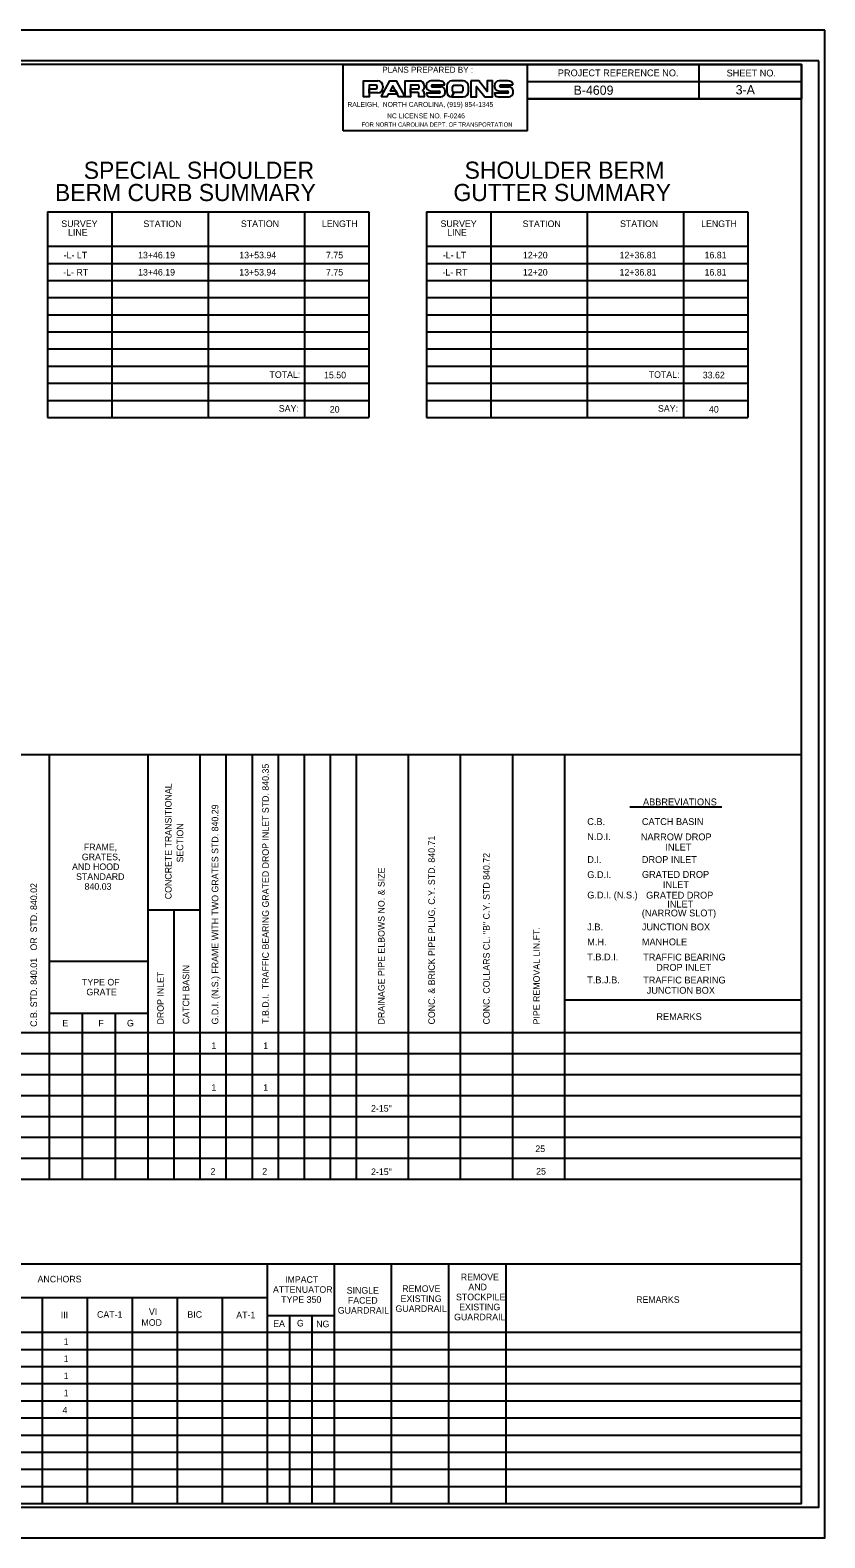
# Model space of a CAD drawing. Extents: x 573850.4 to 573884, y -53328.4 to -53306.4.
# Drawn here: x 573872.44 to 573884.04, y -53328.38 to -53306.38 of the extents above; entities that cross this region are included whole.
import ezdxf

# ---------------------------------------------------------------- set-up
doc = ezdxf.new("R2010")
doc.units = 0
for name, color, linetype in [('Old_Level_2', 7, 'Continuous'), ('Sheet Cutting Line CELL', 7, 'Continuous'), ('Sheet Data Field CELL', 7, 'Continuous'), ('Sheet Pipe Summary CELL', 7, 'Continuous'), ('Sheet Pipe Summary Grid CELL', 7, 'Continuous'), ('Sheet Plot Border Inside CELL', 7, 'Continuous'), ('Sheet Plot Border Outside CELL', 7, 'Continuous'), ('Sheet Summary Combination CELL', 7, 'Continuous'), ('Sheet Summary Combination Grid CELL', 7, 'Continuous')]:
    doc.layers.add(name, color=color, linetype=linetype)

msp = doc.modelspace()

# ---------------------------------------------------------------- linework, layer by layer
at = {"layer": 'Old_Level_2'}
for p, q in [((573877.008, -53306.879), (573879.696, -53306.879)), ((573877.008, -53307.848), (573877.008, -53306.879)), ((573879.696, -53307.848), (573879.696, -53306.879)), ((573877.504, -53307.215), (573877.504, -53307.201)), ((573877.586, -53307.196), (573877.586, -53307.219)), ((573878.114, -53307.219), (573878.114, -53307.193)), ((573878.19, -53307.186), (573878.19, -53307.221)), ((573878.219, -53307.192), (573878.219, -53307.201)), ((573878.278, -53307.265), (573878.409, -53307.268)), ((573878.419, -53307.12), (573878.286, -53307.12)), ((573878.308, -53307.179), (573878.488, -53307.179)), ((573878.436, -53307.209), (573878.308, -53307.209)), ((573878.494, -53307.288), (573878.494, -53307.27)), ((573878.521, -53307.199), (573878.521, -53307.277)), ((573878.591, -53307.354), (573878.623, -53307.291)), ((573878.757, -53307.12), (573878.594, -53307.12)), ((573878.6, -53307.267), (573878.6, -53307.207)), ((573878.623, -53307.182), (573878.729, -53307.182)), ((573878.751, -53307.207), (573878.751, -53307.267)), ((573878.836, -53307.271), (573878.836, -53307.205)), ((573879.214, -53307.192), (573879.214, -53307.201)), ((573879.273, -53307.265), (573879.404, -53307.268)), ((573879.415, -53307.12), (573879.282, -53307.12)), ((573879.303, -53307.179), (573879.483, -53307.179)), ((573879.432, -53307.209), (573879.303, -53307.209)), ((573879.489, -53307.288), (573879.489, -53307.27)), ((573878.295, -53307.354), (573878.432, -53307.354)), ((573878.591, -53307.354), (573878.76, -53307.354)), ((573879.29, -53307.354), (573879.427, -53307.354)), ((573879.696, -53307.848), (573877.008, -53307.848))]:
    msp.add_line(p, q, dxfattribs=at)
for points in [[(573877.487, -53307.182), (573877.384, -53307.182), (573877.384, -53307.236), (573877.385, -53307.296), (573877.385, -53307.354), (573877.302, -53307.354), (573877.302, -53307.12), (573877.514, -53307.12)], [(573877.514, -53307.296), (573877.385, -53307.296), (573877.384, -53307.236), (573877.484, -53307.236)], [(573878.104, -53307.183), (573877.988, -53307.183), (573877.988, -53307.235), (573877.988, -53307.291), (573877.988, -53307.354), (573877.911, -53307.354), (573877.911, -53307.12), (573878.128, -53307.12)], [(573878.19, -53307.303), (573878.19, -53307.354), (573878.111, -53307.354), (573878.111, -53307.3), (573878.101, -53307.291), (573877.988, -53307.291), (573877.988, -53307.235), (573878.1, -53307.235)], [(573878.409, -53307.297), (573878.222, -53307.297), (573878.222, -53307.302)], [(573878.729, -53307.291), (573878.623, -53307.291), (573878.591, -53307.354), (573878.76, -53307.354)], [(573879.404, -53307.297), (573879.217, -53307.297), (573879.217, -53307.302)]]:
    msp.add_lwpolyline(points, dxfattribs=at)
for points in [[(573877.559, -53307.354), (573877.688, -53307.12), (573877.781, -53307.12), (573877.908, -53307.354), (573877.821, -53307.354), (573877.732, -53307.19), (573877.69, -53307.265), (573877.773, -53307.265), (573877.799, -53307.314), (573877.665, -53307.314), (573877.644, -53307.354)], [(573878.872, -53307.12), (573878.872, -53307.354), (573878.951, -53307.354), (573878.951, -53307.202), (573879.073, -53307.354), (573879.185, -53307.354), (573879.185, -53307.12), (573879.108, -53307.12), (573879.108, -53307.276), (573878.985, -53307.12)]]:
    msp.add_lwpolyline(points, close=True, dxfattribs=at)
for centre, major_axis, ratio, start_param, end_param in [((573877.484, -53307.215), (0, 0.0214), 0.93676, 3.141593, 4.712389), ((573877.487, -53307.201), (0, 0.0184), 0.93676, 4.712389, 6.283185), ((573877.514, -53307.196), (0, 0.0765), 0.93676, 4.712389, 6.283185), ((573877.514, -53307.219), (0, 0.0765), 0.93676, 3.141593, 4.712389), ((573878.1, -53307.219), (0, 0.0153), 0.934072, 3.141593, 4.712389), ((573878.104, -53307.193), (0, 0.0107), 0.934072, 4.712389, 6.283185), ((573878.128, -53307.186), (0, 0.0658), 0.934072, 4.712389, 6.283185), ((573878.152, -53307.221), (0, 0.0398), 0.934072, 3.34512, 4.712389), ((573878.147, -53307.303), (0, 0.0459), 0.934072, 4.712389, 5.969561), ((573878.286, -53307.192), (0, 0.0719), 0.934072, 0, 1.570796), ((573878.279, -53307.201), (0, -0.0643), 0.934072, 4.712389, 6.260753), ((573878.266, -53307.302), (0, -0.0474), 0.934072, 4.712389, 5.988639), ((573878.308, -53307.194), (0, 0.0145), 0.934072, 0, 3.141593), ((573878.409, -53307.283), (0, 0.0145), 0.934072, 3.141593, 6.283185), ((573878.419, -53307.219), (0, 0.0994), 0.934072, 5.902203, 6.283185), ((573878.432, -53307.288), (0, 0.0658), 0.934072, 3.141593, 4.712389), ((573878.437, -53307.27), (0, 0.0612), 0.934072, 4.712389, 6.283185), ((573878.434, -53307.181), (0, 0.0582), 0.934072, 4.738699, 5.901866), ((573878.594, -53307.199), (0, 0.0796), 0.924824, 0, 1.570796), ((573878.591, -53307.277), (0, -0.0765), 0.924824, 4.712389, 6.283185), ((573878.623, -53307.207), (0, -0.0245), 0.924824, 3.141593, 4.712389), ((573878.623, -53307.267), (0, -0.0245), 0.924824, 4.712389, 6.283185), ((573878.729, -53307.207), (0, 0.0245), 0.924824, 4.712389, 6.283185), ((573878.729, -53307.267), (0, 0.0245), 0.924824, 3.141593, 4.712389), ((573878.757, -53307.205), (0, 0.0857), 0.924824, 4.712389, 6.283185), ((573878.76, -53307.271), (0, 0.0826), 0.924824, 3.141593, 4.712389), ((573879.282, -53307.192), (0, 0.0719), 0.934072, 0, 1.570796), ((573879.274, -53307.201), (0, -0.0643), 0.934072, 4.712389, 6.260753), ((573879.262, -53307.302), (0, -0.0474), 0.934072, 4.712389, 5.988639), ((573879.303, -53307.194), (0, 0.0145), 0.934072, 0, 3.141593), ((573879.405, -53307.283), (0, 0.0145), 0.934072, 3.141593, 6.283185), ((573879.415, -53307.219), (0, 0.0994), 0.934072, 5.902203, 6.283185), ((573879.427, -53307.288), (0, 0.0658), 0.934072, 3.141593, 4.712389), ((573879.432, -53307.27), (0, 0.0612), 0.934072, 4.712389, 6.283185), ((573879.429, -53307.181), (0, 0.0582), 0.934072, 4.738699, 5.901866), ((573878.295, -53307.201), (0, 0.153), 0.934072, 2.847261, 3.141593), ((573879.29, -53307.201), (0, 0.153), 0.934072, 2.847261, 3.141593)]:
    msp.add_ellipse(centre, major_axis=major_axis, ratio=ratio, start_param=start_param, end_param=end_param, dxfattribs=at)
at = {"layer": 'Sheet Cutting Line CELL'}
for p, q in [((573884.037, -53306.379), (573850.357, -53306.379)), ((573850.357, -53328.379), (573884.037, -53328.379))]:
    msp.add_line(p, q, dxfattribs=at)
at = {"layer": 'Sheet Pipe Summary CELL'}
msp.add_line((573882.532, -53317.719), (573881.192, -53317.719), dxfattribs=at)
at = {"layer": 'Sheet Pipe Summary Grid CELL'}
for p, q in [((573883.697, -53316.954), (573853.697, -53316.956)), ((573872.722, -53323.15), (573872.722, -53316.955)), ((573874.161, -53323.15), (573874.161, -53316.954)), ((573874.921, -53323.15), (573874.921, -53316.954)), ((573875.301, -53323.15), (573875.301, -53316.954)), ((573875.681, -53323.15), (573875.681, -53316.954)), ((573876.061, -53323.15), (573876.061, -53316.954)), ((573876.441, -53323.15), (573876.441, -53316.954)), ((573876.821, -53323.15), (573876.821, -53316.954)), ((573877.201, -53323.15), (573877.201, -53316.954)), ((573877.961, -53323.15), (573877.961, -53316.954)), ((573877.961, -53323.15), (573877.961, -53316.954)), ((573878.721, -53323.15), (573878.721, -53316.954)), ((573878.721, -53323.15), (573878.721, -53316.954)), ((573879.481, -53323.15), (573879.481, -53316.954)), ((573879.481, -53323.15), (573879.481, -53316.954)), ((573880.241, -53323.15), (573880.241, -53316.954)), ((573880.241, -53323.15), (573880.241, -53316.954)), ((573874.921, -53319.219), (573874.161, -53319.219)), ((573874.541, -53323.15), (573874.541, -53319.219)), ((573874.161, -53319.97), (573872.722, -53319.97)), ((573874.161, -53320.726), (573872.722, -53320.726)), ((573873.202, -53323.15), (573873.202, -53320.726)), ((573873.682, -53323.15), (573873.682, -53320.726)), ((573883.697, -53320.535), (573880.241, -53320.535)), ((573883.697, -53321.012), (573853.697, -53321.012)), ((573883.697, -53321.318), (573853.697, -53321.318)), ((573883.697, -53321.318), (573853.697, -53321.318)), ((573883.697, -53321.623), (573853.697, -53321.623)), ((573883.697, -53321.928), (573853.697, -53321.928)), ((573883.697, -53322.234), (573853.697, -53322.234)), ((573883.697, -53322.538), (573853.697, -53322.538)), ((573883.697, -53322.844), (573853.697, -53322.844)), ((573883.697, -53323.15), (573853.697, -53323.15))]:
    msp.add_line(p, q, dxfattribs=at)
at = {"layer": 'Sheet Plot Border Inside CELL'}
msp.add_lwpolyline([(573883.947, -53306.828), (573850.617, -53306.828), (573850.617, -53327.93), (573883.947, -53327.93)], close=True, dxfattribs=at)
at = {"layer": 'Sheet Plot Border Outside CELL'}
msp.add_lwpolyline([(573884.037, -53306.379), (573850.357, -53306.379), (573850.357, -53328.379), (573884.037, -53328.379)], close=True, dxfattribs=at)
at = {"layer": 'Sheet Summary Combination CELL'}
for p, q in [((573882.197, -53306.88), (573882.197, -53307.38)), ((573879.696, -53307.13), (573883.697, -53307.13)), ((573879.696, -53307.38), (573883.697, -53307.38)), ((573875.515, -53309.033), (573875.515, -53309.033)), ((573875.64, -53309.035), (573875.64, -53309.035)), ((573875.821, -53309.031), (573875.821, -53309.031)), ((573875.933, -53309.033), (573875.933, -53309.033)), ((573881.05, -53309.033), (573881.05, -53309.033)), ((573881.175, -53309.035), (573881.175, -53309.035)), ((573881.356, -53309.031), (573881.356, -53309.031)), ((573881.468, -53309.033), (573881.468, -53309.033))]:
    msp.add_line(p, q, dxfattribs=at)
for points in [[(573883.697, -53306.879), (573853.697, -53306.879), (573853.697, -53327.879), (573883.697, -53327.879)], [(573879.696, -53306.879), (573883.697, -53306.879), (573883.697, -53307.38), (573879.696, -53307.38)]]:
    msp.add_lwpolyline(points, close=True, dxfattribs=at)
at = {"layer": 'Sheet Summary Combination Grid CELL'}
for p, q in [((573872.69, -53309.032), (573877.379, -53309.032)), ((573872.69, -53309.032), (573872.69, -53312.032)), ((573873.628, -53309.032), (573873.628, -53312.032)), ((573875.035, -53309.032), (573875.035, -53312.032)), ((573876.441, -53309.032), (573876.441, -53312.032)), ((573877.379, -53309.032), (573877.379, -53312.032)), ((573878.225, -53309.032), (573882.914, -53309.032)), ((573878.225, -53309.032), (573878.225, -53312.032)), ((573879.163, -53309.032), (573879.163, -53312.032)), ((573880.57, -53309.032), (573880.57, -53312.032)), ((573881.976, -53309.032), (573881.976, -53312.032)), ((573882.914, -53309.032), (573882.914, -53312.032)), ((573872.69, -53309.532), (573877.379, -53309.532)), ((573878.225, -53309.532), (573882.914, -53309.532)), ((573872.69, -53309.782), (573877.379, -53309.782)), ((573878.225, -53309.782), (573882.914, -53309.782)), ((573872.69, -53310.032), (573877.379, -53310.032)), ((573878.225, -53310.032), (573882.914, -53310.032)), ((573872.69, -53310.282), (573877.379, -53310.282)), ((573878.225, -53310.282), (573882.914, -53310.282)), ((573872.69, -53310.532), (573877.379, -53310.532)), ((573878.225, -53310.532), (573882.914, -53310.532)), ((573872.69, -53310.782), (573877.379, -53310.782)), ((573872.69, -53310.782), (573877.379, -53310.782)), ((573878.225, -53310.782), (573882.914, -53310.782)), ((573878.225, -53310.782), (573882.914, -53310.782)), ((573872.69, -53311.032), (573877.379, -53311.032)), ((573878.225, -53311.032), (573882.914, -53311.032)), ((573872.69, -53311.282), (573877.379, -53311.282)), ((573878.225, -53311.282), (573882.914, -53311.282)), ((573872.69, -53311.532), (573877.379, -53311.532)), ((573878.225, -53311.532), (573882.914, -53311.532)), ((573872.69, -53311.782), (573877.379, -53311.782)), ((573878.225, -53311.782), (573882.914, -53311.782)), ((573872.69, -53312.032), (573877.379, -53312.032)), ((573878.225, -53312.032), (573882.914, -53312.032)), ((573853.697, -53324.379), (573883.697, -53324.379)), ((573875.896, -53324.379), (573875.896, -53327.879)), ((573876.873, -53324.379), (573876.873, -53327.879)), ((573877.709, -53324.379), (573877.709, -53327.879)), ((573878.545, -53324.379), (573878.545, -53327.879)), ((573879.382, -53324.379), (573879.382, -53327.879)), ((573875.896, -53324.879), (573866.353, -53324.879)), ((573872.615, -53324.879), (573872.615, -53327.879)), ((573873.271, -53324.879), (573873.271, -53327.879)), ((573873.927, -53324.879), (573873.927, -53327.879)), ((573874.584, -53324.879), (573874.584, -53327.879)), ((573875.24, -53324.879), (573875.24, -53327.879)), ((573875.896, -53325.134), (573876.868, -53325.134)), ((573876.221, -53325.134), (573876.222, -53327.879)), ((573876.548, -53325.134), (573876.549, -53327.879)), ((573853.697, -53325.379), (573883.697, -53325.379)), ((573853.697, -53325.629), (573883.697, -53325.629)), ((573853.697, -53325.879), (573883.697, -53325.879)), ((573853.697, -53326.129), (573883.697, -53326.129)), ((573853.697, -53326.379), (573883.697, -53326.379)), ((573853.697, -53326.629), (573883.697, -53326.629)), ((573853.697, -53326.879), (573883.697, -53326.879)), ((573853.697, -53327.129), (573883.697, -53327.129)), ((573853.697, -53327.379), (573883.697, -53327.379)), ((573853.697, -53327.629), (573883.697, -53327.629))]:
    msp.add_line(p, q, dxfattribs=at)

# ---------------------------------------------------------------- texts
at = {"layer": 'Old_Level_2'}
for s, height, rotation, p in [('PLANS PREPARED BY : ', 0.08829, 359.999, (573877.577, -53307.002)), ('RALEIGH,  NORTH CAROLINA, (919) 854-1345', 0.07151, 360, (573877.068, -53307.499)), ('FOR NORTH CAROLINA DEPT. OF TRANSPORTATION', 0.06203, 359.9999, (573877.274, -53307.788)), ('NC LICENSE NO. F-0246', 0.07151, 360, (573877.647, -53307.666))]:
    msp.add_text(s, height=height, rotation=rotation, dxfattribs=at).set_placement(p)
at = {"layer": 'Sheet Data Field CELL'}
for s, p in [('B-4609   ', (573880.369, -53307.323)), ('3-A', (573882.735, -53307.317))]:
    msp.add_text(s, height=0.135, dxfattribs=at).set_placement(p)
at = {"layer": 'Sheet Pipe Summary CELL'}
for s, height, rotation, p in [('T.B.D.I.  TRAFFIC BEARING GRATED DROP INLET STD. 840.35', 0.096, 90, (573875.921, -53320.879)), ('CONCRETE TRANSITIONAL', 0.096, 90, (573874.502, -53319.061)), ('G.D.I. (N.S.) FRAME WITH TWO GRATES STD. 840.29', 0.096, 90, (573875.184, -53320.888)), ('SECTION', 0.096, 90, (573874.673, -53318.524)), ('CONC. & BRICK PIPE PLUG, C.Y. STD. 840.71', 0.096, 90, (573878.345, -53320.888)), ('CONC. COLLARS CL. "B" C.Y. STD 840.72', 0.096, 90, (573879.145, -53320.888)), ('DRAINAGE PIPE ELBOWS NO. & SIZE', 0.096, 90, (573877.611, -53320.888)), ('C.B. STD. 840.01   OR  STD. 840.02', 0.096, 90, (573872.538, -53320.923)), ('GRATED DROP', 0.1, 0.0274, (573881.428, -53319.052)), ('INLET', 0.1, 0.0274, (573881.736, -53319.182)), ('(NARROW SLOT)', 0.1, 0.0274, (573881.365, -53319.312)), ('PIPE REMOVAL LIN.FT.', 0.096, 90, (573879.876, -53320.888)), ('CATCH BASIN', 0.096, 90, (573874.759, -53320.884)), ('DROP INLET', 0.096, 90, (573874.388, -53320.888))]:
    msp.add_text(s, height=height, rotation=rotation, dxfattribs=at).set_placement(p)
for s, height, p in [('ABBREVIATIONS', 0.1, (573881.383, -53317.691)), ('C.B.', 0.1, (573880.569, -53317.978)), ('CATCH BASIN', 0.1, (573881.366, -53317.978)), ('N.D.I.', 0.1, (573880.569, -53318.197)), ('NARROW DROP', 0.1, (573881.351, -53318.201)), ('FRAME,', 0.096, (573873.222, -53318.347)), ('INLET', 0.1, (573881.71, -53318.351)), ('AND HOOD', 0.096, (573873.049, -53318.635)), ('GRATES,', 0.096, (573873.192, -53318.491)), ('D.I.', 0.1, (573880.569, -53318.532)), ('DROP INLET', 0.1, (573881.366, -53318.532)), ('STANDARD', 0.096, (573873.108, -53318.779)), ('G.D.I.', 0.1, (573880.569, -53318.752)), ('GRATED DROP', 0.1, (573881.367, -53318.749)), ('840.03', 0.096, (573873.232, -53318.923)), ('G.D.I. (N.S.)', 0.1, (573880.569, -53319.05)), ('INLET', 0.1, (573881.674, -53318.899)), ('J.B.', 0.1, (573880.569, -53319.515)), ('JUNCTION BOX', 0.1, (573881.366, -53319.515)), ('M.H.', 0.1, (573880.569, -53319.734)), ('MANHOLE', 0.1, (573881.366, -53319.734)), ('T.B.D.I.', 0.1, (573880.569, -53319.953)), ('TRAFFIC BEARING', 0.1, (573881.385, -53319.955)), ('DROP INLET', 0.1, (573881.575, -53320.105)), ('TYPE OF', 0.096, (573873.194, -53320.319)), ('T.B.J.B.', 0.1, (573880.569, -53320.288)), ('TRAFFIC BEARING', 0.1, (573881.385, -53320.29)), ('GRATE', 0.096, (573873.259, -53320.463)), ('JUNCTION BOX', 0.1, (573881.437, -53320.44)), ('REMARKS', 0.1, (573881.578, -53320.824)), ('E', 0.096, (573872.909, -53320.917)), ('F', 0.096, (573873.433, -53320.917)), ('G', 0.096, (573873.851, -53320.917))]:
    msp.add_text(s, height=height, dxfattribs=at).set_placement(p)
at = {"layer": 'Sheet Summary Combination CELL'}
for s, height, p in [('PROJECT REFERENCE NO.', 0.1, (573880.14, -53307.053)), ('SHEET NO.', 0.1, (573882.603, -53307.055)), ('SURVEY', 0.096, (573872.893, -53309.252)), ('LINE', 0.096, (573872.991, -53309.378)), ('STATION', 0.096, (573874.091, -53309.253)), ('STATION', 0.096, (573875.514, -53309.252)), ('LENGTH', 0.096, (573876.696, -53309.252)), ('SURVEY', 0.096, (573878.427, -53309.252)), ('LINE', 0.096, (573878.526, -53309.378)), ('STATION', 0.096, (573879.626, -53309.253)), ('STATION', 0.096, (573881.048, -53309.252)), ('LENGTH', 0.096, (573882.231, -53309.252)), ('-L- LT', 0.096, (573872.927, -53309.71)), ('13+46.19', 0.096, (573874.013, -53309.71)), ('13+53.94', 0.096, (573875.49, -53309.71)), ('7.75', 0.096, (573876.756, -53309.71)), ('-L- LT', 0.096, (573878.461, -53309.71)), ('12+20', 0.096, (573879.63, -53309.71)), ('12+36.81', 0.096, (573881.041, -53309.71)), ('16.81', 0.096, (573882.281, -53309.71)), ('-L- RT', 0.096, (573872.921, -53309.96)), ('13+46.19', 0.096, (573874.013, -53309.96)), ('13+53.94', 0.096, (573875.49, -53309.96)), ('7.75', 0.096, (573876.756, -53309.96)), ('-L- RT', 0.096, (573878.456, -53309.96)), ('12+20', 0.096, (573879.63, -53309.96)), ('12+36.81', 0.096, (573881.041, -53309.96)), ('16.81', 0.096, (573882.281, -53309.96)), ('TOTAL:', 0.096, (573875.931, -53311.453)), ('15.50', 0.096, (573876.727, -53311.46)), ('TOTAL:', 0.096, (573881.466, -53311.453)), ('33.62', 0.096, (573882.255, -53311.46)), ('SAY:', 0.096, (573876.067, -53311.947)), ('20', 0.096, (573876.811, -53311.96)), ('SAY:', 0.096, (573881.601, -53311.947)), ('40', 0.096, (573882.345, -53311.96)), ('1', 0.096, (573875.084, -53321.246)), ('1', 0.096, (573875.84, -53321.246)), ('1', 0.096, (573875.084, -53321.856)), ('1', 0.096, (573875.84, -53321.856)), ('2-15"', 0.096, (573877.413, -53322.161)), ('25', 0.096, (573879.811, -53322.75)), ('2', 0.096, (573875.07, -53323.079)), ('2', 0.096, (573875.826, -53323.079)), ('2-15"', 0.096, (573877.413, -53323.086)), ('25', 0.096, (573879.823, -53323.079)), ('ANCHORS', 0.096, (573872.546, -53324.652)), ('IMPACT', 0.096, (573876.158, -53324.658)), ('REMOVE', 0.096, (573877.868, -53324.791)), ('REMOVE', 0.096, (573878.723, -53324.621)), ('AND', 0.096, (573878.834, -53324.767)), ('ATTENUATOR', 0.096, (573875.982, -53324.804)), ('TYPE 350', 0.096, (573876.102, -53324.95)), ('SINGLE', 0.096, (573877.058, -53324.816)), ('FACED', 0.096, (573877.075, -53324.962)), ('EXISTING', 0.096, (573877.844, -53324.937)), ('STOCKPILE', 0.096, (573878.653, -53324.913)), ('REMARKS', 0.096, (573881.282, -53324.951)), ('III', 0.096, (573872.885, -53325.175)), ('CAT-1', 0.096, (573873.414, -53325.168)), ('VI', 0.096, (573874.171, -53325.127)), ('BIC', 0.096, (573874.733, -53325.168)), ('AT-1', 0.096, (573875.446, -53325.176)), ('GUARDRAIL', 0.096, (573876.927, -53325.108)), ('GUARDRAIL', 0.096, (573877.77, -53325.083)), ('GUARDRAIL', 0.096, (573878.625, -53325.205)), ('EXISTING', 0.096, (573878.699, -53325.059)), ('MOD', 0.096, (573874.062, -53325.285)), ('EA', 0.096, (573875.985, -53325.302)), ('G', 0.096, (573876.332, -53325.295)), ('NG', 0.096, (573876.613, -53325.306)), ('1', 0.096, (573872.927, -53325.564)), ('1', 0.096, (573872.927, -53325.814)), ('1', 0.096, (573872.927, -53326.064)), ('1', 0.096, (573872.927, -53326.314)), ('4', 0.096, (573872.91, -53326.564))]:
    msp.add_text(s, height=height, dxfattribs=at).set_placement(p)
for s, p in [('SPECIAL SHOULDER', (573873.22, -53308.549)), ('SHOULDER BERM', (573878.779, -53308.548)), ('BERM CURB SUMMARY', (573872.8, -53308.874)), ('GUTTER SUMMARY', (573878.616, -53308.873))]:
    msp.add_text(s, height=0.25, rotation=0.0119, dxfattribs=at).set_placement(p)

doc.saveas('drawing.dxf')
